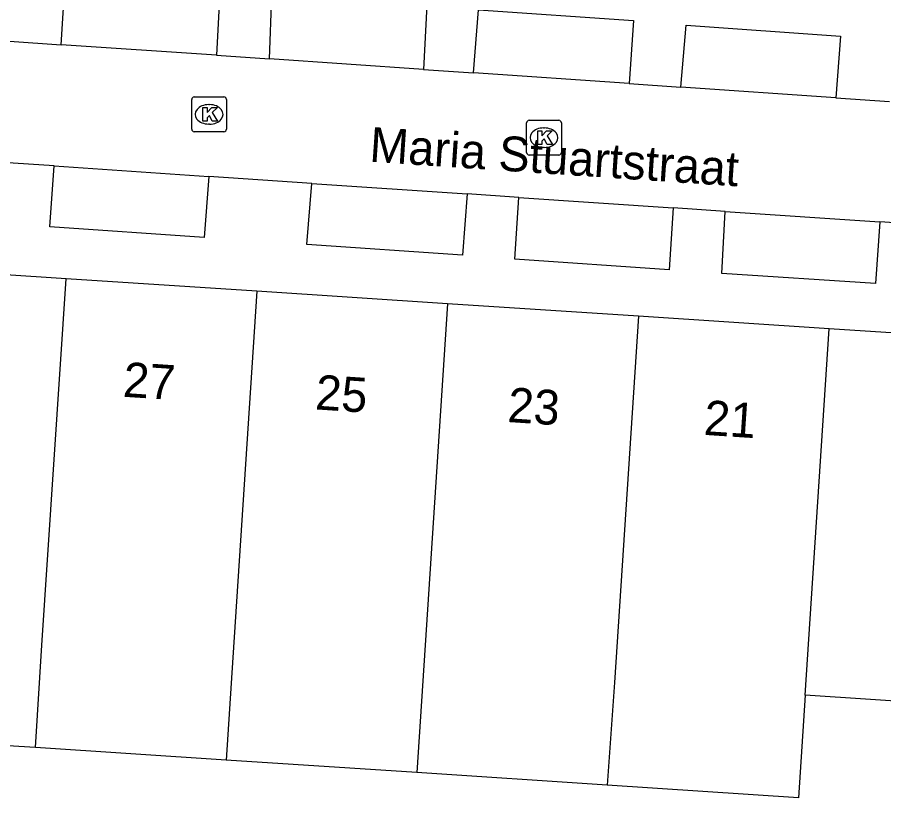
# Model space of a CAD drawing. Extents: x 159961 to 160856, y 382704 to 383353.
# Drawn here: x 160654.94 to 160679.86, y 382868.5 to 382890.94 of the extents above; entities that cross this region are included whole.
import ezdxf

# ---------------------------------------------------------------- set-up
doc = ezdxf.new("R2010")
doc.units = 0
for name, color, linetype in [('IMGEO_Kolk', 7, 'Continuous'), ('IMGEO_Openbare_ruimte_label', 7, 'Continuous'), ('IMGEO_Pand', 7, 'Continuous'), ('IMGEO_Pand_nummerreeks', 7, 'Continuous'), ('IMGEO_Rijbaan_lokaal_open', 7, 'Continuous'), ('IMGEO_Voetpad_open', 7, 'Continuous')]:
    doc.layers.add(name, color=color, linetype=linetype)

msp = doc.modelspace()

# ---------------------------------------------------------------- linework, layer by layer
at = {"layer": 'IMGEO_Kolk'}
for p, q in [((160660.032, 382888.65), (160660.884, 382888.65)), ((160659.957, 382887.724), (160659.957, 382888.576)), ((160660.445, 382888.43), (160660.47, 382888.43)), ((160660.958, 382888.576), (160660.958, 382887.724)), ((160660.468, 382887.87), (160660.443, 382887.87)), ((160669.587, 382887.054), (160669.587, 382887.906)), ((160669.662, 382887.98), (160670.514, 382887.98)), ((160670.588, 382887.906), (160670.588, 382887.054)), ((160660.884, 382887.65), (160660.032, 382887.65)), ((160670.075, 382887.76), (160670.1, 382887.76)), ((160670.098, 382887.2), (160670.073, 382887.2)), ((160670.514, 382886.98), (160669.662, 382886.98))]:
    msp.add_line(p, q, dxfattribs=at)
for points in [[(160660.032, 382888.65), (160660.884, 382888.65)], [(160659.957, 382887.724), (160659.957, 382888.576)], [(160660.278, 382888.35), (160660.401, 382888.35), (160660.401, 382888.199), (160660.531, 382888.35), (160660.695, 382888.35), (160660.549, 382888.199), (160660.702, 382887.95), (160660.55, 382887.95), (160660.465, 382888.114), (160660.401, 382888.047), (160660.401, 382887.95), (160660.278, 382887.95), (160660.278, 382888.35)], [(160660.958, 382888.576), (160660.958, 382887.724)], [(160669.587, 382887.054), (160669.587, 382887.906)], [(160669.662, 382887.98), (160670.514, 382887.98)], [(160670.588, 382887.906), (160670.588, 382887.054)], [(160660.884, 382887.65), (160660.032, 382887.65)], [(160669.908, 382887.68), (160670.031, 382887.68), (160670.031, 382887.529), (160670.161, 382887.68), (160670.325, 382887.68), (160670.179, 382887.529), (160670.332, 382887.28), (160670.18, 382887.28), (160670.095, 382887.444), (160670.031, 382887.377), (160670.031, 382887.28), (160669.908, 382887.28), (160669.908, 382887.68)], [(160670.514, 382886.98), (160669.662, 382886.98)]]:
    msp.add_lwpolyline(points, dxfattribs=at)
for centre, start, end in [((160660.034, 382888.574), 91.552, 178.448), ((160660.034, 382888.574), 91.552, 178.448), ((160660.882, 382888.574), 1.552, 88.448), ((160660.882, 382888.574), 1.552, 88.448), ((160669.664, 382887.904), 91.552, 178.448), ((160669.664, 382887.904), 91.552, 178.448), ((160670.512, 382887.904), 1.552, 88.448), ((160670.512, 382887.904), 1.552, 88.448), ((160660.034, 382887.726), 181.552, 268.448), ((160660.034, 382887.726), 181.552, 268.448), ((160660.882, 382887.726), 271.552, 358.448), ((160660.882, 382887.726), 271.552, 358.448), ((160669.664, 382887.056), 181.552, 268.448), ((160669.664, 382887.056), 181.552, 268.448), ((160670.512, 382887.056), 271.552, 358.448), ((160670.512, 382887.056), 271.552, 358.448)]:
    msp.add_arc(centre, 0.0765, start, end, dxfattribs=at)
for centre, major_axis, ratio, start_param, end_param in [((160660.444, 382888.15), (-0.387, 0.002), 0.722429, 4.712389, 7.853982), ((160660.469, 382888.15), (-0.39, 0.002), 0.717154, 1.570796, 4.712389), ((160670.074, 382887.48), (-0.387, 0.002), 0.722429, 4.712389, 7.853982), ((160670.099, 382887.48), (-0.39, 0.002), 0.717154, 1.570796, 4.712389)]:
    msp.add_ellipse(centre, major_axis=major_axis, ratio=ratio, start_param=start_param, end_param=end_param, dxfattribs=at)
at = {"layer": 'IMGEO_Pand'}
for points in [[(160656.342, 382883.424), (160650.704, 382883.794)], [(160655.464, 382869.938), (160655.651, 382872.887), (160656.342, 382883.424)], [(160661.83, 382883.064), (160656.342, 382883.424)], [(160661.83, 382883.064), (160661.139, 382872.527), (160660.946, 382869.579)], [(160667.318, 382882.704), (160661.83, 382883.064)], [(160667.318, 382882.704), (160666.431, 382869.219)], [(160672.806, 382882.343), (160667.318, 382882.704)], [(160672.806, 382882.343), (160672.114, 382871.807), (160671.903, 382868.86)], [(160678.294, 382881.983), (160672.806, 382882.343)], [(160677.602, 382871.446), (160678.294, 382881.983)], [(160683.783, 382881.623), (160678.294, 382881.983)], [(160677.602, 382871.446), (160677.408, 382868.499), (160671.903, 382868.86)], [(160683.091, 382871.086), (160677.602, 382871.446)], [(160655.464, 382869.938), (160649.881, 382870.278)], [(160660.946, 382869.579), (160655.464, 382869.938)], [(160666.431, 382869.219), (160660.946, 382869.579)], [(160671.903, 382868.86), (160666.431, 382869.219)]]:
    msp.add_lwpolyline(points, dxfattribs=at)
at = {"layer": 'IMGEO_Rijbaan_lokaal_open'}
for points in [[(160654.718, 382890.255), (160656.207, 382890.153)], [(160660.669, 382889.848), (160656.207, 382890.153)], [(160660.669, 382889.848), (160662.19, 382889.744)], [(160666.619, 382889.441), (160662.19, 382889.744)], [(160666.619, 382889.441), (160668.062, 382889.342)], [(160672.537, 382889.036), (160668.062, 382889.342)], [(160672.537, 382889.036), (160674.026, 382888.934)], [(160678.484, 382888.629), (160674.026, 382888.934)], [(160678.484, 382888.629), (160680.022, 382888.524)], [(160656.004, 382886.667), (160654.523, 382886.768)], [(160656.004, 382886.667), (160660.45, 382886.366)], [(160663.411, 382886.166), (160660.45, 382886.366)], [(160663.411, 382886.166), (160667.882, 382885.863)], [(160669.361, 382885.763), (160667.882, 382885.863)], [(160669.361, 382885.763), (160673.806, 382885.462)], [(160675.298, 382885.361), (160673.806, 382885.462)], [(160675.298, 382885.361), (160679.744, 382885.06)], [(160686.085, 382884.631), (160679.744, 382885.06)]]:
    msp.add_lwpolyline(points, dxfattribs=at)
at = {"layer": 'IMGEO_Voetpad_open'}
for points in [[(160656.207, 382890.153), (160656.315, 382891.98), (160660.766, 382891.686), (160660.669, 382889.848)], [(160662.19, 382889.744), (160662.264, 382891.576), (160666.722, 382891.292), (160666.619, 382889.441)], [(160668.062, 382889.342), (160668.204, 382891.158), (160672.661, 382890.85), (160672.537, 382889.036)], [(160674.026, 382888.934), (160674.179, 382890.717), (160678.618, 382890.398), (160678.484, 382888.629)], [(160660.45, 382886.366), (160660.315, 382884.611), (160655.88, 382884.916), (160656.004, 382886.667)], [(160667.882, 382885.863), (160667.748, 382884.099), (160663.27, 382884.411), (160663.411, 382886.166)], [(160673.806, 382885.462), (160673.693, 382883.677), (160669.246, 382883.987), (160669.361, 382885.763)], [(160679.744, 382885.06), (160679.627, 382883.288), (160675.201, 382883.574), (160675.298, 382885.361)]]:
    msp.add_lwpolyline(points, dxfattribs=at)

# ---------------------------------------------------------------- texts
at = {"layer": 'IMGEO_Openbare_ruimte_label'}
msp.add_text('Maria Stuartstraat', height=1, rotation=356.1593, dxfattribs=at).set_placement((160665.052, 382886.791))
at = {"layer": 'IMGEO_Pand_nummerreeks'}
for s, rotation, p in [('27', 356.2471, (160657.962, 382880.031)), ('25', 356.2451, (160663.493, 382879.667)), ('23', 356.2451, (160669.024, 382879.304)), ('21', 356.2471, (160674.668, 382878.935))]:
    msp.add_text(s, height=1, rotation=rotation, dxfattribs=at).set_placement(p)

doc.saveas('drawing.dxf')
